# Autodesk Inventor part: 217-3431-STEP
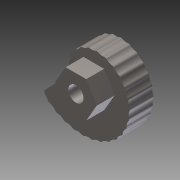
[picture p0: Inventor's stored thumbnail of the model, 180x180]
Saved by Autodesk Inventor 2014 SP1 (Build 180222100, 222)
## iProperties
Created: 2014-06
Part Number: 217-3431-STEP
Material: Generic
Document SubType Name: Modeling
Designer: Michael
Density: 6.03657 g/cm^3
Appearance: Default
Mass: 13.6078 g
Surface Area: 13.5118 cm^2
Volume: 2.25422 cm^3
Title: 217-3431-STEP.STEP
Description: STEP AP214
Creation Date: 2013-12-10
Sending System: SolidWorks 2013
Preprocessor: SwSTEP 2.0
Author: Michael
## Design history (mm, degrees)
node "217-3431-STEP1"
node "Fillet1"
node "Base1"
